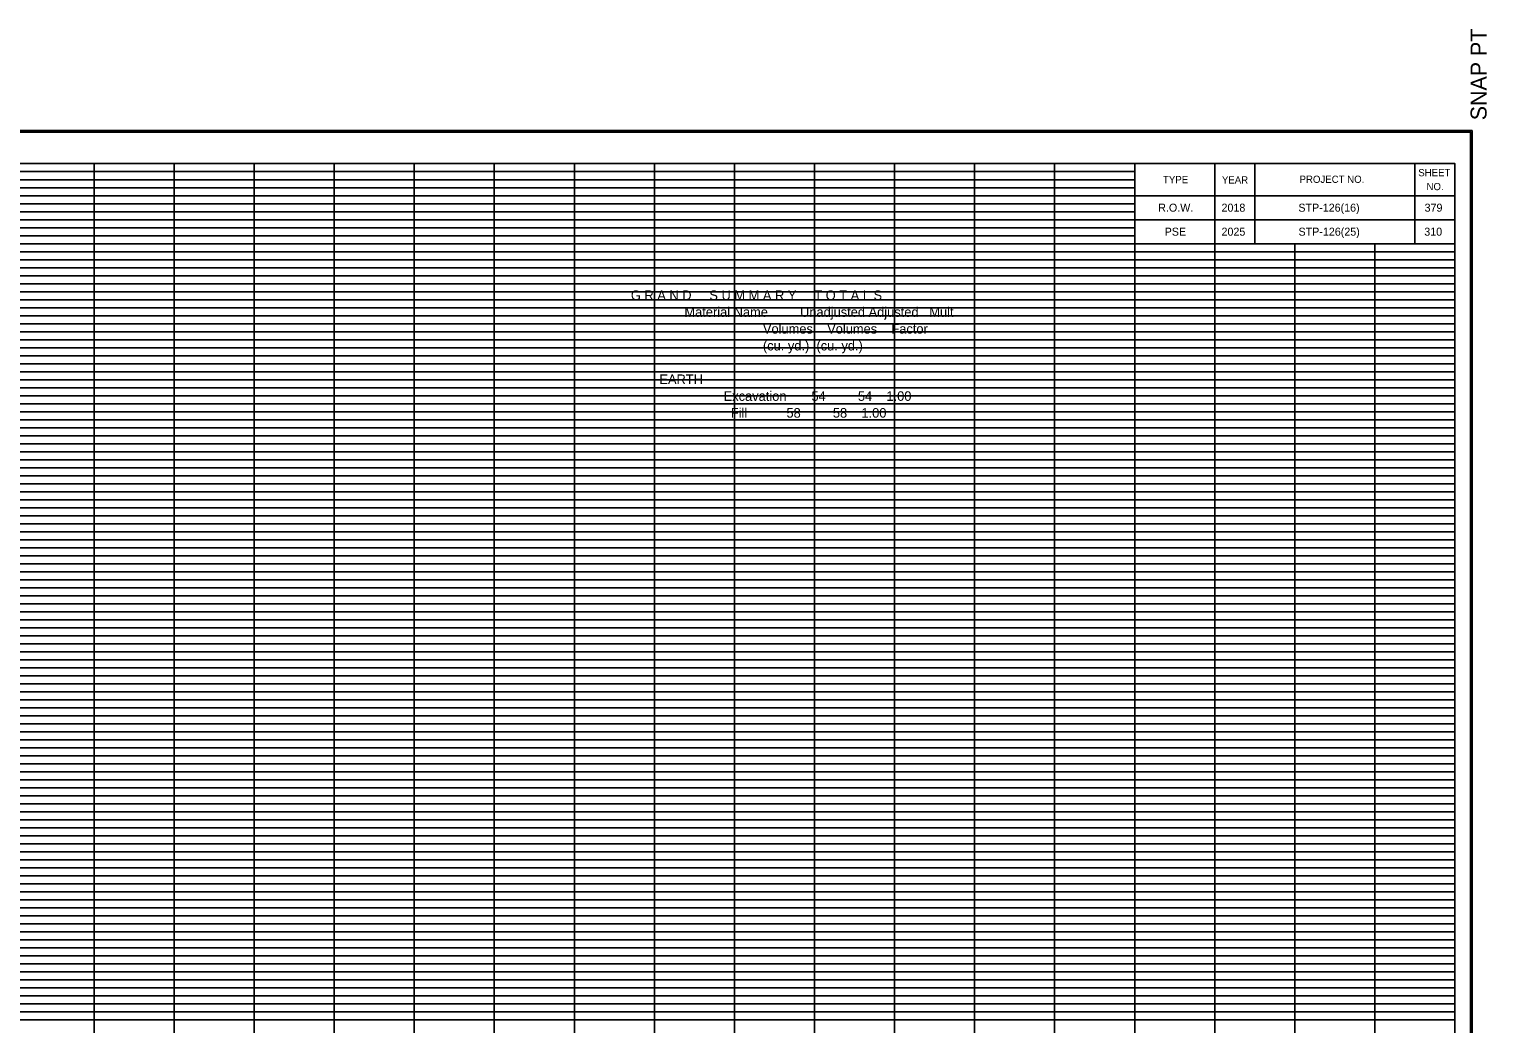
# Model space of a CAD drawing. Extents: x 980 to 1324, y 978 to 1227.
# Drawn here: x 1141.9 to 1324, y 1102.5 to 1226.8 of the extents above; entities that cross this region are included whole.
import ezdxf

# ---------------------------------------------------------------- set-up
doc = ezdxf.new("R2010")
doc.units = 0
for name, color, linetype in [('DESIGN - SCRATCH - User 1', 7, 'Continuous'), ('DESIGN - SHEET - Corner Text', 7, 'Continuous'), ('DESIGN - SHEET - Light Grid', 7, 'Continuous'), ('DESIGN - SHEET - Linework', 7, 'Continuous'), ('DESIGN - SHEET - Plot Shape', 7, 'Continuous'), ('DESIGN - TYPICAL - Finished Grade and Subgrade', 7, 'Continuous'), ('DESIGN - TYPICAL - Text', 7, 'Continuous')]:
    doc.layers.add(name, color=color, linetype=linetype)

# ---------------------------------------------------------------- blocks, each defined once
blk = doc.blocks.new('XSTSHT')
at = {"layer": 'DESIGN - SCRATCH - User 1'}
for p, q in [((28.5, 20.45), (28.5, 20.45)), ((29.24, 20.45), (29.24, 20.45)), ((30.49, 20.45), (30.49, 20.45)), ((31.74, 20.45), (31.74, 20.45)), ((28.5, 20.15), (28.5, 20.15)), ((29.24, 20.15), (29.24, 20.15)), ((30.49, 20.15), (30.49, 20.15)), ((31.74, 20.15), (31.74, 20.15))]:
    blk.add_line(p, q, dxfattribs=at)
at = {"layer": 'DESIGN - SHEET - Light Grid'}
for p, q in [((8, 20.9), (16, 20.9)), ((8, 20.8), (16, 20.8)), ((16, 20.9), (24, 20.9)), ((16, 20.8), (24, 20.8)), ((24, 20.9), (28, 20.9)), ((24, 20.8), (28, 20.8)), ((8, 20.7), (16, 20.7)), ((8, 20.6), (16, 20.6)), ((16, 20.7), (24, 20.7)), ((16, 20.6), (24, 20.6)), ((24, 20.7), (28, 20.7)), ((24, 20.6), (28, 20.6)), ((8, 20.5), (16, 20.5)), ((8, 20.4), (16, 20.4)), ((16, 20.5), (24, 20.5)), ((16, 20.4), (24, 20.4)), ((24, 20.5), (28, 20.5)), ((24, 20.4), (28, 20.4)), ((8, 20.3), (16, 20.3)), ((16, 20.3), (24, 20.3)), ((24, 20.3), (28, 20.3)), ((8, 20.2), (16, 20.2)), ((8, 20.1), (16, 20.1)), ((16, 20.2), (24, 20.2)), ((16, 20.1), (24, 20.1)), ((24, 20.2), (28, 20.2)), ((24, 20.1), (28, 20.1)), ((8, 19.9), (16, 19.9)), ((16, 19.9), (24, 19.9)), ((24, 19.9), (32, 19.9)), ((8, 19.8), (16, 19.8)), ((8, 19.7), (16, 19.7)), ((16, 19.8), (24, 19.8)), ((16, 19.7), (24, 19.7)), ((24, 19.8), (32, 19.8)), ((24, 19.7), (32, 19.7)), ((8, 19.6), (16, 19.6)), ((8, 19.5), (16, 19.5)), ((16, 19.6), (24, 19.6)), ((16, 19.5), (24, 19.5)), ((24, 19.6), (32, 19.6)), ((24, 19.5), (32, 19.5)), ((8, 19.4), (16, 19.4)), ((16, 19.4), (24, 19.4)), ((24, 19.4), (32, 19.4)), ((8, 19.3), (16, 19.3)), ((8, 19.2), (16, 19.2)), ((16, 19.3), (24, 19.3)), ((16, 19.2), (24, 19.2)), ((24, 19.3), (32, 19.3)), ((24, 19.2), (32, 19.2)), ((8, 19.1), (16, 19.1)), ((16, 19.1), (24, 19.1)), ((24, 19.1), (32, 19.1)), ((8, 18.9), (16, 18.9)), ((8, 18.8), (16, 18.8)), ((16, 18.9), (24, 18.9)), ((16, 18.8), (24, 18.8)), ((24, 18.9), (32, 18.9)), ((24, 18.8), (32, 18.8)), ((8, 18.7), (16, 18.7)), ((8, 18.6), (16, 18.6)), ((16, 18.7), (24, 18.7)), ((16, 18.6), (24, 18.6)), ((24, 18.7), (32, 18.7)), ((24, 18.6), (32, 18.6)), ((8, 18.5), (16, 18.5)), ((8, 18.4), (16, 18.4)), ((16, 18.5), (24, 18.5)), ((16, 18.4), (24, 18.4)), ((24, 18.5), (32, 18.5)), ((24, 18.4), (32, 18.4)), ((8, 18.3), (16, 18.3)), ((16, 18.3), (24, 18.3)), ((24, 18.3), (32, 18.3)), ((8, 18.2), (16, 18.2)), ((8, 18.1), (16, 18.1)), ((16, 18.2), (24, 18.2)), ((16, 18.1), (24, 18.1)), ((24, 18.2), (32, 18.2)), ((24, 18.1), (32, 18.1)), ((8, 17.9), (16, 17.9)), ((16, 17.9), (24, 17.9)), ((24, 17.9), (32, 17.9)), ((8, 17.8), (16, 17.8)), ((8, 17.7), (16, 17.7)), ((16, 17.8), (24, 17.8)), ((16, 17.7), (24, 17.7)), ((24, 17.8), (32, 17.8)), ((24, 17.7), (32, 17.7)), ((8, 17.6), (16, 17.6)), ((8, 17.5), (16, 17.5)), ((16, 17.6), (24, 17.6)), ((16, 17.5), (24, 17.5)), ((24, 17.6), (32, 17.6)), ((24, 17.5), (32, 17.5)), ((8, 17.4), (16, 17.4)), ((16, 17.4), (24, 17.4)), ((24, 17.4), (32, 17.4)), ((8, 17.3), (16, 17.3)), ((8, 17.2), (16, 17.2)), ((16, 17.3), (24, 17.3)), ((16, 17.2), (24, 17.2)), ((24, 17.3), (32, 17.3)), ((24, 17.2), (32, 17.2)), ((8, 17.1), (16, 17.1)), ((16, 17.1), (24, 17.1)), ((24, 17.1), (32, 17.1)), ((8, 16.9), (16, 16.9)), ((8, 16.8), (16, 16.8)), ((16, 16.9), (24, 16.9)), ((16, 16.8), (24, 16.8)), ((24, 16.9), (32, 16.9)), ((24, 16.8), (32, 16.8)), ((8, 16.7), (16, 16.7)), ((8, 16.6), (16, 16.6)), ((16, 16.7), (24, 16.7)), ((16, 16.6), (24, 16.6)), ((24, 16.7), (32, 16.7)), ((24, 16.6), (32, 16.6)), ((8, 16.5), (16, 16.5)), ((8, 16.4), (16, 16.4)), ((16, 16.5), (24, 16.5)), ((16, 16.4), (24, 16.4)), ((24, 16.5), (32, 16.5)), ((24, 16.4), (32, 16.4)), ((8, 16.3), (16, 16.3)), ((16, 16.3), (24, 16.3)), ((24, 16.3), (32, 16.3)), ((8, 16.2), (16, 16.2)), ((8, 16.1), (16, 16.1)), ((16, 16.2), (24, 16.2)), ((16, 16.1), (24, 16.1)), ((24, 16.2), (32, 16.2)), ((24, 16.1), (32, 16.1)), ((8, 15.9), (16, 15.9)), ((16, 15.9), (24, 15.9)), ((24, 15.9), (32, 15.9)), ((8, 15.8), (16, 15.8)), ((8, 15.7), (16, 15.7)), ((16, 15.8), (24, 15.8)), ((16, 15.7), (24, 15.7)), ((24, 15.8), (32, 15.8)), ((24, 15.7), (32, 15.7)), ((8, 15.6), (16, 15.6)), ((8, 15.5), (16, 15.5)), ((16, 15.6), (24, 15.6)), ((16, 15.5), (24, 15.5)), ((24, 15.6), (32, 15.6)), ((24, 15.5), (32, 15.5)), ((8, 15.4), (16, 15.4)), ((8, 15.3), (16, 15.3)), ((16, 15.4), (24, 15.4)), ((16, 15.3), (24, 15.3)), ((24, 15.4), (32, 15.4)), ((24, 15.3), (32, 15.3)), ((8, 15.2), (16, 15.2)), ((16, 15.2), (24, 15.2)), ((24, 15.2), (32, 15.2)), ((8, 15.1), (16, 15.1)), ((16, 15.1), (24, 15.1)), ((24, 15.1), (32, 15.1)), ((8, 14.9), (16, 14.9)), ((8, 14.8), (16, 14.8)), ((16, 14.9), (24, 14.9)), ((16, 14.8), (24, 14.8)), ((24, 14.9), (32, 14.9)), ((24, 14.8), (32, 14.8)), ((8, 14.7), (16, 14.7)), ((8, 14.6), (16, 14.6)), ((16, 14.7), (24, 14.7)), ((16, 14.6), (24, 14.6)), ((24, 14.7), (32, 14.7)), ((24, 14.6), (32, 14.6)), ((8, 14.5), (16, 14.5)), ((8, 14.4), (16, 14.4)), ((16, 14.5), (24, 14.5)), ((16, 14.4), (24, 14.4)), ((24, 14.5), (32, 14.5)), ((24, 14.4), (32, 14.4)), ((8, 14.3), (16, 14.3)), ((16, 14.3), (24, 14.3)), ((24, 14.3), (32, 14.3)), ((8, 14.2), (16, 14.2)), ((8, 14.1), (16, 14.1)), ((16, 14.2), (24, 14.2)), ((16, 14.1), (24, 14.1)), ((24, 14.2), (32, 14.2)), ((24, 14.1), (32, 14.1)), ((8, 13.9), (16, 13.9)), ((16, 13.9), (24, 13.9)), ((24, 13.9), (32, 13.9)), ((8, 13.8), (16, 13.8)), ((8, 13.7), (16, 13.7)), ((16, 13.8), (24, 13.8)), ((16, 13.7), (24, 13.7)), ((24, 13.8), (32, 13.8)), ((24, 13.7), (32, 13.7)), ((8, 13.6), (16, 13.6)), ((8, 13.5), (16, 13.5)), ((16, 13.6), (24, 13.6)), ((16, 13.5), (24, 13.5)), ((24, 13.6), (32, 13.6)), ((24, 13.5), (32, 13.5)), ((8, 13.4), (16, 13.4)), ((8, 13.3), (16, 13.3)), ((16, 13.4), (24, 13.4)), ((16, 13.3), (24, 13.3)), ((24, 13.4), (32, 13.4)), ((24, 13.3), (32, 13.3)), ((8, 13.2), (16, 13.2)), ((16, 13.2), (24, 13.2)), ((24, 13.2), (32, 13.2)), ((8, 13.1), (16, 13.1)), ((16, 13.1), (24, 13.1)), ((24, 13.1), (32, 13.1)), ((8, 12.9), (16, 12.9)), ((8, 12.8), (16, 12.8)), ((16, 12.9), (24, 12.9)), ((16, 12.8), (24, 12.8)), ((24, 12.9), (32, 12.9)), ((24, 12.8), (32, 12.8)), ((8, 12.7), (16, 12.7)), ((8, 12.6), (16, 12.6)), ((16, 12.7), (24, 12.7)), ((16, 12.6), (24, 12.6)), ((24, 12.7), (32, 12.7)), ((24, 12.6), (32, 12.6)), ((8, 12.5), (16, 12.5)), ((8, 12.4), (16, 12.4)), ((16, 12.5), (24, 12.5)), ((16, 12.4), (24, 12.4)), ((24, 12.5), (32, 12.5)), ((24, 12.4), (32, 12.4)), ((8, 12.3), (16, 12.3)), ((16, 12.3), (24, 12.3)), ((24, 12.3), (32, 12.3)), ((8, 12.2), (16, 12.2)), ((8, 12.1), (16, 12.1)), ((16, 12.2), (24, 12.2)), ((16, 12.1), (24, 12.1)), ((24, 12.2), (32, 12.2)), ((24, 12.1), (32, 12.1)), ((8, 11.9), (16, 11.9)), ((16, 11.9), (24, 11.9)), ((24, 11.9), (32, 11.9)), ((8, 11.8), (16, 11.8)), ((8, 11.7), (16, 11.7)), ((16, 11.8), (24, 11.8)), ((16, 11.7), (24, 11.7)), ((24, 11.8), (32, 11.8)), ((24, 11.7), (32, 11.7)), ((8, 11.6), (16, 11.6)), ((8, 11.5), (16, 11.5)), ((16, 11.6), (24, 11.6)), ((16, 11.5), (24, 11.5)), ((24, 11.6), (32, 11.6)), ((24, 11.5), (32, 11.5)), ((8, 11.4), (16, 11.4)), ((8, 11.3), (16, 11.3)), ((16, 11.4), (24, 11.4)), ((16, 11.3), (24, 11.3)), ((24, 11.4), (32, 11.4)), ((24, 11.3), (32, 11.3)), ((8, 11.2), (16, 11.2)), ((16, 11.2), (24, 11.2)), ((24, 11.2), (32, 11.2)), ((8, 11.1), (16, 11.1)), ((16, 11.1), (24, 11.1)), ((24, 11.1), (32, 11.1)), ((8, 10.9), (16, 10.9)), ((8, 10.8), (16, 10.8)), ((16, 10.9), (24, 10.9)), ((16, 10.8), (24, 10.8)), ((24, 10.9), (32, 10.9)), ((24, 10.8), (32, 10.8)), ((8, 10.7), (16, 10.7)), ((8, 10.6), (16, 10.6)), ((16, 10.7), (24, 10.7)), ((16, 10.6), (24, 10.6)), ((24, 10.7), (32, 10.7)), ((24, 10.6), (32, 10.6)), ((8, 10.5), (16, 10.5)), ((8, 10.4), (16, 10.4)), ((16, 10.5), (24, 10.5)), ((16, 10.4), (24, 10.4)), ((24, 10.5), (32, 10.5)), ((24, 10.4), (32, 10.4)), ((8, 10.3), (16, 10.3)), ((16, 10.3), (24, 10.3)), ((24, 10.3), (32, 10.3))]:
    blk.add_line(p, q, dxfattribs=at)
at = {"layer": 'DESIGN - SHEET - Linework'}
for p, q in [((-1.823, 21.414), (32.217, 21.414)), ((32.217, 21.414), (32.217, -0.414)), ((15, 0), (15, 21)), ((16, 0), (16, 21)), ((17, 0), (17, 21)), ((18, 0), (18, 21)), ((19, 0), (19, 21)), ((20, 0), (20, 21)), ((21, 0), (21, 21)), ((22, 0), (22, 21)), ((23, 0), (23, 21)), ((24, 0), (24, 21)), ((25, 0), (25, 21)), ((26, 0), (26, 21)), ((27, 0), (27, 21)), ((0, 20), (28, 20)), ((28, 0), (28, 20)), ((29, 0), (29, 20)), ((30, 0), (30, 20)), ((31, 0), (31, 20)), ((0, 19), (32, 19)), ((0, 18), (32, 18)), ((0, 17), (32, 17)), ((0, 16), (32, 16)), ((0, 15), (32, 15)), ((0, 14), (32, 14)), ((0, 13), (32, 13)), ((0, 12), (32, 12)), ((0, 11), (32, 11))]:
    blk.add_line(p, q, dxfattribs=at)
for points in [[(0, 21), (0, 0), (32, 0), (32, 21), (0, 21)], [(28, 21), (28, 20), (32, 20), (32, 21), (31.5, 21), (31.5, 20), (29.5, 20), (29.5, 21), (29, 21), (29, 20), (32, 20), (28, 20), (28, 20.3), (32, 20.3), (32, 20.6), (28, 20.6)]]:
    blk.add_lwpolyline(points, dxfattribs=at)
at = {"layer": 'DESIGN - SHEET - Plot Shape'}
for points in [[(-1.803, 21.394), (32.197, 21.394), (32.197, -0.394), (-1.803, -0.394)], [(-0.85, 21), (32, 21), (32, -0.25), (-0.85, -0.25)]]:
    blk.add_lwpolyline(points, close=True, dxfattribs=at)
at = {"layer": 'DESIGN - SHEET - Corner Text'}
blk.add_text('  SNAP PT', height=0.2, rotation=90, dxfattribs=at).set_placement((32.397, 21.394))
for s, p in [('TYPE', (28.354, 20.756)), ('YEAR', (29.09, 20.752)), ('PROJECT NO.', (30.06, 20.76)), ('SHEET', (31.543, 20.843)), ('NO.', (31.646, 20.669))]:
    blk.add_text(s, height=0.09, dxfattribs=at).set_placement(p)

msp = doc.modelspace()

# ---------------------------------------------------------------- block references
at = {"layer": 'DESIGN - TYPICAL - Finished Grade and Subgrade', "xscale": 10, "yscale": 10}
msp.add_blockref('XSTSHT', (1000, 1000), dxfattribs=at)

# ---------------------------------------------------------------- texts
at = {"layer": 'DESIGN - SHEET - Corner Text'}
for s, p in [('R.O.W.', (1282.94, 1204)), ('2018', (1290.85, 1204)), ('STP-126(16)', (1300.45, 1204)), ('379', (1316.22, 1204)), ('PSE', (1283.75, 1201)), ('2025', (1290.85, 1201)), ('STP-126(25)', (1300.47, 1201)), ('310', (1316.18, 1201))]:
    msp.add_text(s, height=1, dxfattribs=at).set_placement(p)
at = {"layer": 'DESIGN - TYPICAL - Text'}
for s, p in [('G R A N D     S U M M A R Y     T O T A L S', (1217.06, 1192.96)), ('               Material Name         Unadjusted Adjusted   Mult', (1217.06, 1190.86)), ('                                     Volumes    Volumes    Factor', (1217.06, 1188.76)), ('                                     (cu. yd.)  (cu. yd.)', (1217.06, 1186.66)), ('        ---------------------------- ---------- ---------- ------', (1217.06, 1184.56)), ('        EARTH', (1217.06, 1182.46)), ('                          Excavation       54         54    1.00', (1217.06, 1180.36)), ('                            Fill           58         58    1.00', (1217.06, 1178.26))]:
    msp.add_text(s, height=1.2, dxfattribs=at).set_placement(p)

doc.saveas('drawing.dxf')
